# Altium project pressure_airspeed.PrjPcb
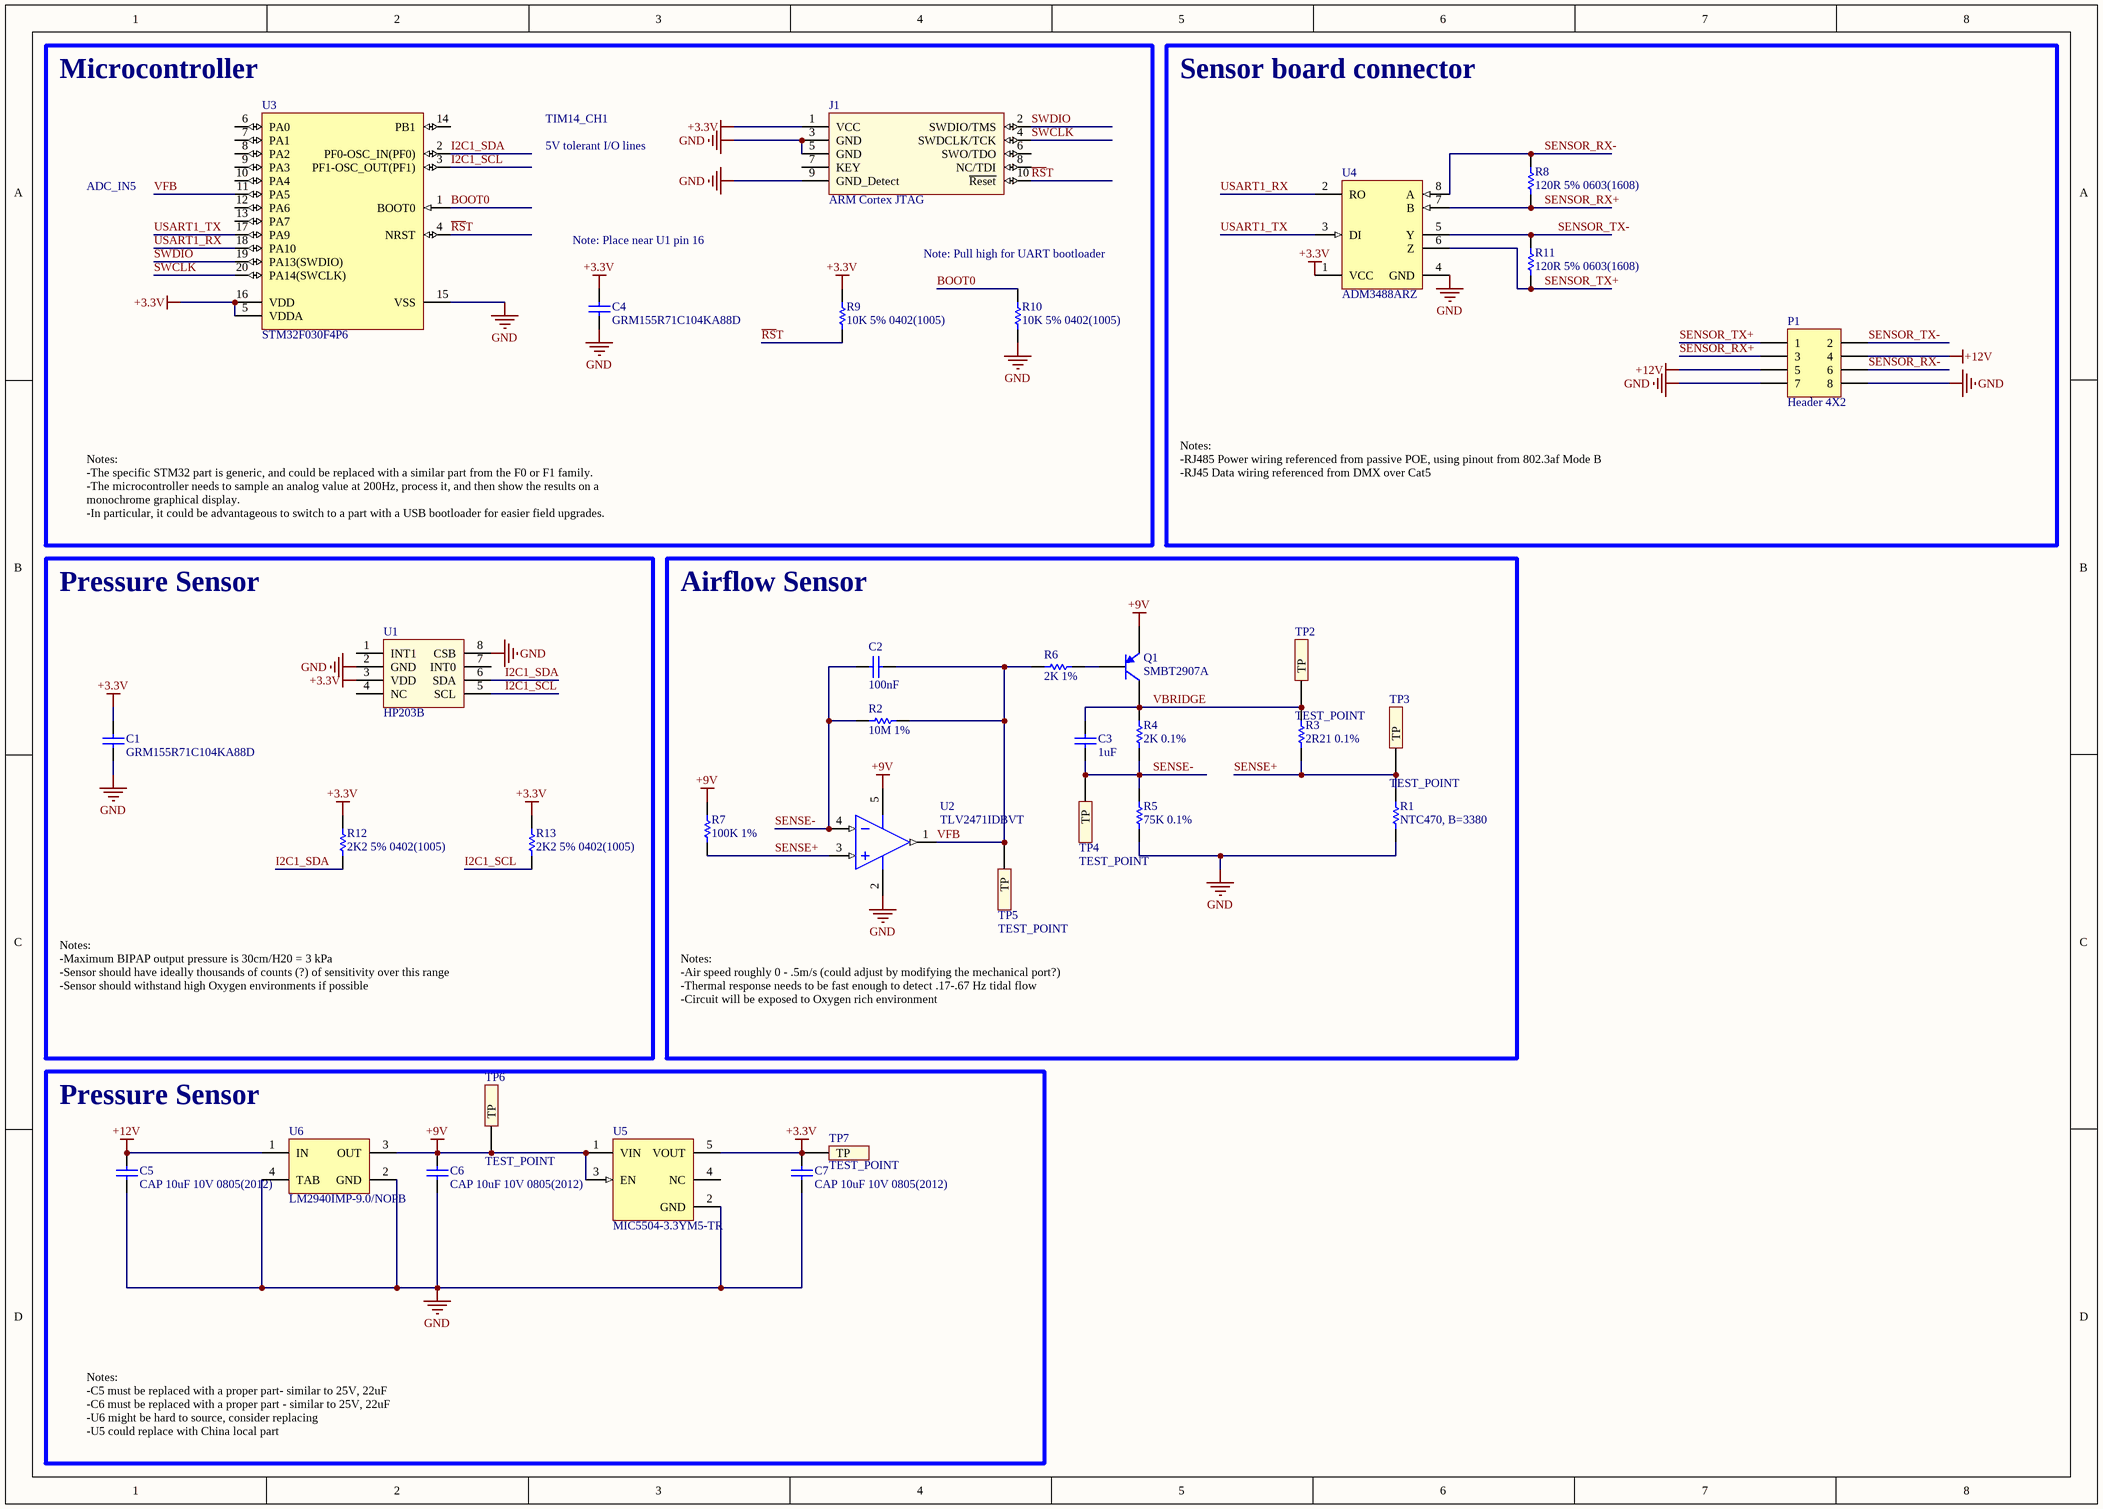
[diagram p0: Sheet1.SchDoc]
1 sheet, 35 parts. Net scope: global (net labels, ports and power ports of the same name join across sheets).
Board file: PCB1.PcbDoc

## Sheet Sheet1.SchDoc
size A3; DocumentNumber: 1; SheetNumber: 1; SheetTotal: 1

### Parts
C1  GRM155R71C104KA88D  [CAPC1005X55X25ML05T10]
C2  100nF  [CAPC1005X55X25ML05T10]
C3  1uF  [CAPC1005X55X25ML05T10]
C4  GRM155R71C104KA88D  [CAPC1005X55X25ML05T10]
C5  CAP 10uF 10V 0805(2012)  [CAPC0805(2012)145_N]
C6  CAP 10uF 10V 0805(2012)  [CAPC0805(2012)145_N]
C7  CAP 10uF 10V 0805(2012)  [CAPC0805(2012)145_N]
J1  ARM Cortex JTAG  [1.27mm 2x5 SMD Header - no paste]
P1  Header 4X2  [HDR2X4]
Q1  SMBT2907A  [INF-SOT23_N]
R1  NTC470, B=3380  [RESC1005X40X25NL05T05]
R2  10M 1%  [RESC1005X40X25ML05T10]
R3  2R21 0.1%  [RESC1005X40X25ML05T10]
R4  2K 0.1%  [RESC1005X40X25ML05T10]
R5  75K 0.1%  [RESC1005X40X25ML05T10]
R6  2K 1%  [RESC1005X40X25NL05T05]
R7  100K 1%  [RESC1005X40X25ML05T10]
R8  120R 5% 0603(1608)  [RESC0603(1608)_L]
R9  10K 5% 0402(1005)  [RESC0402(1005)_N]
R10  10K 5% 0402(1005)  [RESC0402(1005)_N]
R11  120R 5% 0603(1608)  [RESC0603(1608)_L]
R12  2K2 5% 0402(1005)  [RESC0402(1005)_N]
R13  2K2 5% 0402(1005)  [RESC0402(1005)_N]
TP2  TEST_POINT  [TP-SMD-1mm]  (no BOM)
TP3  TEST_POINT  [TP-SMD-1mm]  (no BOM)
TP4  TEST_POINT  [TP-SMD-1mm]  (no BOM)
TP5  TEST_POINT  [TP-SMD-1mm]  (no BOM)
TP6  TEST_POINT  [TP-SMD-1mm]  (no BOM)
TP7  TEST_POINT  [TP-SMD-1mm]  (no BOM)
U1  HP203B  [HP203B]
U2  TLV2471IDBVT  [DBV0005A_L]
U3  STM32F030F4P6  [STM-TSSOP20_L]
U4  ADM3488ARZ  [ADI-R-8_L]
U5  MIC5504-3.3YM5-TR  [MCHP-SOT-23-M5_V]
U6  LM2940IMP-9.0/NOPB  [DCY0004A_L]

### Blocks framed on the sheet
Microcontroller: C4 J1 R9 R10 U3
Sensor board connector: P1 R8 R11 U4
Pressure Sensor: C1 R12 R13 U1
Airflow Sensor: C2 C3 Q1 R1-R7 TP2-TP5 U2
Pressure Sensor: C5-C7 TP6 TP7 U5 U6

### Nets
+3.3V: C1.2 C4.2 C7.2 J1.1(VCC) R9.1 R12.2 R13.2 TP7.1(TP) U1.3(VDD) U3.5(VDDA) U3.16(VDD) U4.1(VCC) U5.5(VOUT)
+9V: C6.2 Q1.2(E) R7.1 TP6.1(TP) U2.5(VDD) U5.1(VIN) U5.3(EN) U6.3(OUT)
+12V: C5.2 P1.4 P1.5 U6.1(IN)
GND: C1.1 C4.1 C5.1 C6.1 C7.1 J1.3(GND) J1.5(GND) J1.9(GND_Detect) P1.7 P1.8 R1.1 R5.1 R10.2 U1.2(GND) U1.8(CSB) U2.2(GND) U3.15(VSS) U4.4(GND) U5.2(GND) U6.2(GND) U6.4(TAB)
~{RS}T: J1.10(~{Reset}) R9.2 U3.4(NRST)
BOOT0: R10.1 U3.1(BOOT0)
I2C1_SCL: R13.1 U1.5(SCL) U3.3(PF1-OSC_OUT(PF1))
I2C1_SDA: R12.1 U1.6(SDA) U3.2(PF0-OSC_IN(PF0))
SENSE+: R1.2 R3.1 R7.2 TP3.1(TP) U2.3(IN+)
SENSE-: C2.2 C3.2 R2.2 R4.1 R5.2 TP4.1(TP) U2.4(IN-)
SENSOR_RX+: P1.3 R8.1 U4.7(B)
SENSOR_RX-: P1.6 R8.2 U4.8(A)
SENSOR_TX+: P1.1 R11.1 U4.6(Z)
SENSOR_TX-: P1.2 R11.2 U4.5(Y)
SWCLK: J1.4(SWDCLK/TCK) U3.20(PA14(SWCLK))
SWDIO: J1.2(SWDIO/TMS) U3.19(PA13(SWDIO))
USART1_RX: U3.18(PA10) U4.2(RO)
USART1_TX: U3.17(PA9) U4.3(DI)
VBRIDGE: C3.1 Q1.3(C) R3.2 R4.2 TP2.1(TP)
VFB: C2.1 R2.1 R6.2 TP5.1(TP) U2.1(OUT) U3.11(PA5)
NetQ1_1: Q1.1(B) R6.1

Not connected (* = marked no-connect by the designer): J1 6(SWO/TDO) 7(KEY) 8(NC/TDI); U1 1(INT1) 4(NC) 7(INT0); U3 6(PA0) 7(PA1) 8(PA2) 9(PA3) 10(PA4) 12(PA6) 13(PA7) 14(PB1); U5 4(NC)

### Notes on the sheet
- TIM14_CH1
- 5V tolerant I/O lines
- ADC_IN5
- Note: Place near U1 pin 16
- (near R10) Note: Pull high for UART bootloader
- Notes:
  -RJ485 Power wiring referenced from passive POE, using pinout from 802.3af Mode B
  -RJ45 Data wiring referenced from DMX over Cat5
- Notes:
  -The specific STM32 part is generic, and could be replaced with a similar part from the F0 or F1 family.
  -The microcontroller needs to sample an analog value at 200Hz, process it, and then show the results on a monochrome graphical display.
  -In particular, it could be advantageous to switch to a part with a USB bootloader for easier field upgrades.
- Notes:
  -Maximum BIPAP output pressure is 30cm/H20 = 3 kPa
  -Sensor should have ideally thousands of counts (?) of sensitivity over this range
  -Sensor should withstand high Oxygen environments if possible
- Notes:
  -Air speed roughly 0 - .5m/s (could adjust by modifying the mechanical port?)
  -Thermal response needs to be fast enough to detect .17-.67 Hz tidal flow
  -Circuit will be exposed to Oxygen rich environment
- Notes:
  -C5 must be replaced with a proper part- similar to 25V, 22uF
  -C6 must be replaced with a proper part - similar to 25V, 22uF
  -U6 might be hard to source, consider replacing
  -U5 could replace with China local part

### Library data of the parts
C1 C3 C4 = CMP-2100-03641-1: Chip Capacitor, 0.1 uF, +/- 10%, 16 V, -55 to 125 degC, 0402 (1005 Metric), RoHS, Tape and Reel; Manufacturer: Murata; Material: Ceramic; Insulation Resistance: 10GR; Voltage: 16V; Dielectric: X7R; Capacitance: 100nF
C2 = CMP-2100-03641-1: Chip Capacitor, 0.1 uF, +/- 10%, 16 V, -55 to 125 degC, 0402 (1005 Metric), RoHS, Tape and Reel; Manufacturer: Murata; Material: Ceramic; Insulation Resistance: 10GR; Voltage: 16V; Dielectric: X7R
C5-C7 = CMP-1036-04922-1: CAP 10uF 10V ±10% 0805 (2012 Metric) Thickness 1.45mm SMD; Tolerance: Â±10%; Case-EIA: 0805; Case-Metric: 2012
J1 = ARM Cortex JTAG: Arm Cortex 10-pin JTAG connector; Manufacturer: Unknown/Generic
P1 = Header 4X2: Header, 4-Pin, Dual row
Q1 = CMP-1178-00003-1: PNP Silicon Switching Transistor, 60 V VCEO, 600 mA IC, SOT23, Reel, Green; Manufacturer: Infineon; VCBO (max): 60 V; VCE: 10 V; IC: 150 mA; IC (max): 600 mA; Green: TRUE; VEBO (max): 5 V; ICBO (max): 10 nA
R1 R6 = CMP-2002-01187-1: Manufacturer: Panasonic; Part Number: ERT-J0EV474J
R2-R5 R7 = CMP-2002-07472-1: Part Number: RC0402FR-071KL; Manufacturer: Yageo / Phycomp
R8 R11 = CMP-1012-00052-1: 120R 0.1W 5% 0603 (1608 Metric)  SMD; Case-EIA: 0603; Value: 120.00 Ohm; Case-Metric: 1608
R9 R10 = CMP-1011-00098-1: 10K 0.063W 5% 0402 (1005 Metric)  SMD; Case-Metric: 1005; Value: 10000.00 Ohm; Case-EIA: 0402
R12 R13 = CMP-1011-00082-1: 2K2 0.063W 5% 0402 (1005 Metric)  SMD; Value: 2200.00 Ohm; Case-EIA: 0402; Case-Metric: 1005
TP2-TP7 = TEST_POINT: Test point
U1 = HP203B: PRECISION BAROMETER AND ALTIMETER SENSOR; Manufacturer: HopeRF
U2 = CMP-0271-00230-3: Single Low-Power Rail-to-Rail Input / Output Operational Amplifier, 2.7 to 6 V, -40 to 125 degC, 5-pin SOT23 (DBV5), Green (RoHS & no Sb/Br); Manufacturer: Texas Instruments; Number of Channels: 1; Vio (25C)(Max)(mV): 2.2; Total Supply Voltage(Max)(+5V is 5, +/-5V is 10): 6; CMRR(Min)(dB): 61; Total Supply Voltage(Min)(+5V is 5, +/-5V is 10): 2.7; Iq per channel(Max)(mA): 0.75; Sub Family: Low Supply Voltage Amplifier (<=2.7V), Precision Amplifier; Offset Drift(Typ)(uV/C): 0.4; Slew Rate(Typ)(V/us): 1.4; IIB(Max)(pA): 50; Vn at 1kHz(Typ)(nV/rtHz): 15
U3 = CMP-0304-00039-2: ARM Cortex-M0 32-bit MCU, 16 KB Flash, 4 KB Internal RAM, 15 I/Os, 20-pin TSSOP, -40 to 85 degC, Tube; I/Os (High Current): 15; FLASH Size (Prog) (kB): 16; Internal RAM Size (kB): 4; Supply Voltage(Vcc) min (V): 2.4; Operating Frequency(F) (Processor speed) (MHz): 48
U4 = CMP-0535-00058-1: 3.3 V Slew Rate Limited, Full-Duplex, RS-485/RS-422 Transceivers, 3 to 3.6 V, -40 to 85 degC, 8-Pin SOIC (R-8), RoHS, Tube; Manufacturer: Analog Devices; Guaranteed Data Rate: 0.25 Mbps; Receiver Hysteresis: 50 mV; Number of Drivers: 1; Duplex: Full
U5 = CMP-2000-07604-1: Single LDO, 2.5 to 5.5 V, Fixed Out 3.3 V, 0.3 A, -40 to 125 degC, 5-Pin SOT-23 (M5), RoHS, Tape and Reel; Manufacturer: Microchip; Number of Regulators: 1; Dropout Voltage: 160mV; Output Current: 300mA; Min Input Voltage: 2.5V; Nominal Output Voltage: 3.3V; Max Input Voltage: 5.5V; Min Current Limit: 400mA
U6 = CMP-0062-01727-3: 1A Low Dropout Regulator, 4-pin SOT-223, Pb-Free; Manufacturer: Texas Instruments; PackageTopMarking: XYTT*L0EB; PowerWise: N; CompType: LDO IC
